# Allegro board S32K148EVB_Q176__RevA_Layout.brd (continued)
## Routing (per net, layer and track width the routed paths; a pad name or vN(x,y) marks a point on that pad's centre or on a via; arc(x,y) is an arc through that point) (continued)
PTC16/MII_RMII_RX_ER/QSPI_B_I_2: length 3.3
  TOP w0.279: v1(44,41.62) 44.37,41.99 44.37,42.03 44.55,42.21 U13.10
  TOP w0.406: R230.2 43.6,41.26 43.95,41.62 43.95,41.62 v1(44,41.62)
  BOTTOM w0.279: R230.2 43.6,41.26 43.95,41.62 43.95,41.62 v1(44,41.62)
PTC16/MII_RMII_RX_ER/QSPI_B_IO7: length 4.9
  TOP w0.279: R195.1 42.35,47.71 v1(42.41,47.66) 42.41,47.41 42.77,47.04 44.31,47.04 44.55,46.8 U13.5
  BOTTOM w0.279: v1(42.41,47.66) 42.35,47.71 R195.1
PTC17/MII_RMII_RX_DV: length 103.3
  TOP w0.406: v1(43.32,51.7) 43.32,50.21 43.37,50.16 R196.2 ; R81.2 v1(102.68,67.52)
  L6_INT_2 w0.191: v1(43.32,51.7) 43.32,50.2 44.21,49.31 44.21,47.55 50.98,40.78 55.84,40.78 56.43,41.37 83.98,41.37 84.04,41.43 87.93,45.32 87.93,51.35 88.31,51.72 93.6,57.01 93.87,57.01 93.87,57.01 96.03,57.01 96.31,57.29 96.31,57.31 98.98,59.98 98.98,60.45 95.1,64.34 95.1,66.87 94.72,67.24 94.72,71.9 94.81,71.98 v1(94.81,72.63)
  BOTTOM w0.406: v1(102.68,67.52) 102.27,67.94 102.27,70.3 101.82,70.75 98.82,70.75 96.94,72.63 v1(94.81,72.63)
PTC17/MII_RMII_RX_DV/QSPI_B_I_1: length 3.2
  TOP w0.279: U13.11 v1(45.05,41.72) 44.95,41.72 44.62,41.39 R231.2
  BOTTOM w0.279: v1(45.05,41.72) 44.95,41.72 44.62,41.39 R231.2
PTC17/MII_RMII_RX_DV/QSPI_B_I_2: length 33.1
  TOP w0.16: U8.64 v1(54.65,54.93) ; U7.56 v1(58.98,52.93)
  TOP w0.406: R231.1 v1(44.62,39.11)
  L3_INT_1 w0.191: 52.74,54.93 50.86,54.93 46.92,50.99 46.92,45.72 43.8,42.61 43.8,42.15 43.12,41.47 43.12,38.92 43.4,38.64 44.14,38.64 v1(44.62,39.11)
  L3_INT_1 w0.203: 52.74,54.93 v1(54.65,54.93)
  BOTTOM w0.16: v1(58.98,52.93) 57.39,52.93 55.39,54.93 v1(54.65,54.93)
PTC17/MII_RMII_RX_DV/QSPI_B_IO6: length 4.2
  TOP w0.279: R196.1 v1(43.37,47.75) 44.25,47.75 45.05,46.95 U13.4
  BOTTOM w0.279: v1(43.37,47.75) R196.1
PTC18/FTM7_CH4: length 47.2
  TOP w0.16: U8.83 v1(54.18,45.42)
  BOTTOM w0.191: J2.3 42.68,82.51 43.49,81.7 43.49,76.03 41.5,74.03 41.5,59.53 48.7,52.32 48.7,52.25 48.74,52.21 48.74,51.77
  BOTTOM w0.203: v1(54.18,45.42) 53.84,45.08 53.29,45.08 49.8,48.58 49.8,49.31 48.76,50.35 48.76,51.76 48.74,51.77
PTC19/FTM7_CH5/ADC0_SE25: length 71
  TOP w0.16: U8.85 v1(52.77,44.42) ; U7.72 v1(58.98,44.93)
  L3_INT_1 w0.191: 52.74,44.4 50.63,42.29 50.63,33.82 49.03,32.21 49.03,26.59 v1(48.87,26.43)
  L3_INT_1 w0.203: v1(52.77,44.42) 52.74,44.4
  L6_INT_2 w0.191: v1(48.87,26.43) 50.17,27.73 61.38,27.73 62.35,26.75 62.35,26.19 63.01,25.53 69.02,25.53 71.33,27.85 85,27.85 J5.11
  BOTTOM w0.16: v1(58.98,44.93) 58.48,44.42 v1(52.77,44.42)
PTC20/FTM7_CH6: length 48.4
  TOP w0.16: U8.86 v1(54.65,43.92)
  BOTTOM w0.191: J2.6 37.95,81.39 37.95,78.4 37.93,78.38 37.93,62.57 48.43,52.08 48.43,51.92 48.42,51.91 48.42,51.64 48.43,51.63 48.43,50.2
  BOTTOM w0.203: v1(54.65,43.92) 52.59,43.92 49.47,47.04 49.47,49.16 48.43,50.2
PTC21/FTM7_CH7/FTM7_FLT0: length 50.8
  TOP w0.16: U8.87 v1(54.18,43.42)
  BOTTOM w0.191: J2.9 35.41,81.39 35.41,76.84 34.32,75.74 34.32,65.75 37.65,62.41 37.65,62.41 48.08,51.97 48.08,50.72
  BOTTOM w0.203: v1(54.18,43.42) 54.13,43.47 53.85,43.47 53.81,43.51 53.12,43.51 53.08,43.47 52.57,43.47 48.47,47.57 48.47,49.13 48.09,49.51 48.09,50.72 48.08,50.72
PTC22/FTM7_FLT1: length 51.4
  TOP w0.16: U8.88 v1(54.65,42.92)
  BOTTOM w0.191: J2.12 35.1,81.41 35.1,76.97 34,75.88 34,65.61 47.76,51.84 47.76,50.87 47.76,50.86 47.76,50.59 47.76,50.58 47.76,49.37 48.15,48.99 48.15,47.44 52.47,43.11 52.94,43.11
  BOTTOM w0.203: v1(54.65,42.92) 53.9,42.92 53.67,43.15 53.27,43.15 53.23,43.11 52.94,43.11
PTC23/LPSPI0_SCK/ADC0_SE26: length 28.3
  TOP w0.16: v1(57.85,39.78) 57.78,39.78 57.78,40.98 ; U7.73 v1(59.79,44.12)
  L3_INT_1 w0.191: v1(57.85,39.78) 57.51,39.44 57.51,39.11 57.82,38.8 59.12,38.8 61.2,36.72 61.2,33.85 58.88,31.54 55.71,31.54 54.97,30.8 52.39,30.8 J4.1
  BOTTOM w0.16: v1(57.85,39.78) 59.79,41.72 v1(59.79,44.12)
PTC24/FTM4_CH0: length 58.6
  TOP w0.16: v1(58.32,39.27) 58.32,39.73 58.31,39.75 58.31,39.97 58.28,39.99 58.28,40.98
  BOTTOM w0.191: 52.72,42.61 52.53,42.61 47.83,47.31 47.83,48.86 47.43,49.25 47.43,51.39 47.43,51.4 47.43,51.73 41.04,58.12 40.77,58.12 40.76,58.11 40.72,58.11 33.64,65.19 33.64,72.96 30.36,76.24 30.36,81.41 J2.15
  BOTTOM w0.203: v1(58.32,39.27) 57.67,39.27 55.43,41.51 55.17,41.77 54.96,41.77 54.66,42.06 53.26,42.06 52.72,42.61
PTC25/FTM4_CH1: length 61.5
  TOP w0.16: 58.78,40.98 v1(58.78,39.79)
  BOTTOM w0.191: 40.9,57.8 39.6,57.8 27.82,69.57 27.82,81.41 J2.18
  BOTTOM w0.203: 40.9,57.8 47.1,51.59 47.1,49.13 47.5,48.73 47.5,47.17 52.45,42.23 52.54,42.23 53.06,41.71 54.52,41.71 54.86,41.36 55.08,41.36 57.65,38.79 58.52,38.79 58.8,39.07 58.8,39.77 v1(58.78,39.79)
PTC26/FTM4_CH3: length 63.4
  TOP w0.16: 59.79,40.98 v1(59.79,39.79)
  BOTTOM w0.191: 59.47,38.82 59.09,38.44 57.29,38.44 54.37,41.36 52.86,41.36 47.18,47.04 47.18,48.59 46.76,49.01 46.76,50.31 39.6,57.48 39.46,57.48 25.28,71.66 25.28,81.41 J2.21
  BOTTOM w0.203: v1(59.79,39.79) 59.79,39.14 59.47,38.82
PTC27/FTM4_CH4/FTM4_CH4/ADC0_SE: length 24.3
  TOP w0.16: U7.76 v1(61.29,44.59) ; 60.79,40.98 v1(60.79,39.79)
  L3_INT_1 w0.191: 61.24,38.62 61.52,38.34 61.52,33.72 59.02,31.22 55.84,31.22 55.1,30.48 54.61,30.48 J4.4
  L3_INT_1 w0.203: 61.24,38.62 60.79,39.07 v1(60.79,39.79)
  BOTTOM w0.16: v1(60.79,39.79) 60.79,40.31 61.29,40.81 v1(61.29,44.59)
PTC28: length 9.6
  TOP w0.203: 62.29,40.98 v1(62.29,39.3) ; U7.79 v1(62.79,44.12)
  TOP w0.279: R246.2 62.29,39.3 v1(62.29,39.3)
  BOTTOM w0.203: 62.29,38.62 v1(62.29,39.3) 62.29,40.19 62.64,40.54 62.64,40.67 62.79,40.82 v1(62.79,44.12)
  BOTTOM w0.406: 62.29,38.62 62.29,38.35 R583.2
PTC28/FTM4_CH7/FTM4_CH7/ADC0_SE: length 17.7
  TOP w0.406: v1(63.51,37.59) 63.31,37.79 R246.1
  L3_INT_1 w0.191: v1(63.51,37.59) 63.85,37.25 63.85,31.44 62.34,29.93 62.34,29.04 61.38,28.07 56.94,28.07 J4.7
PTC29/FTM5_CH2/FTM5_CH2/ADC0_SE: length 21.3
  TOP w0.16: U7.82 v1(64.29,44.59) ; 63.79,40.98 v1(63.79,39.79)
  L3_INT_1 w0.191: 63.3,38.62 62.47,37.79 62.47,32.33 59.9,29.76 59.9,29.64 59.43,29.17 J4.10
  L3_INT_1 w0.203: v1(63.79,39.79) 63.79,39.11 63.3,38.62
  BOTTOM w0.16: v1(64.29,44.59) 64.29,40.89 63.79,40.39 v1(63.79,39.79)
PTC30/FTM5_CH4/FXIO_D0/LPI2C1_S: length 40.3
  TOP w0.16: U7.84 v1(65.29,44.59) ; 64.79,40.98 v1(64.79,39.79)
  TOP w0.406: R320.1 v1(58.13,12.37) ; v1(58.15,17.71) 62.19,21.75 62.19,27.9 J4.13
  L3_INT_1 w0.191: 63.87,38.62 62.8,37.55 62.8,32.1 60.92,30.22 J4.13
  L3_INT_1 w0.203: v1(64.79,39.79) 64.79,39.14 64.27,38.62 63.87,38.62
  BOTTOM w0.16: v1(64.79,39.79) 64.79,40.25 65.29,40.75 v1(65.29,44.59)
  BOTTOM w0.406: v1(58.13,12.37) 58.13,12.96 58.15,12.98 v1(58.15,17.71)
PTC31/FTM5_CH6/FXIO_D1/LPI2C1_S: length 55.6
  TOP w0.16: U7.86 v1(66.29,44.59) ; 65.79,40.98 v1(65.79,39.79)
  TOP w0.406: R313.1 40.35,12.43 42.84,14.92 48.93,14.92 50.15,16.14 57.4,16.14 64.76,23.49 64.76,27.87 J4.16
  L3_INT_1 w0.191: 65.79,38.62 65.79,31.5 J4.16
  L3_INT_1 w0.203: 65.79,38.62 v1(65.79,39.79)
  BOTTOM w0.16: v1(65.79,39.79) 65.79,40.1 66.29,40.61 v1(66.29,44.59)
PTD0/FTM0_CH2/FTM2_CH0/TRACE_D0: length 60.3
  TOP w0.16: U7.4 v1(75.79,63.24) ; U8.8 v1(75.8,67.57)
  TOP w0.406: R122.2 95.72,60.03 v1(95.92,59.83)
  L3_INT_1 w0.191: J6.29 69.66,78.85 69.66,75.19 75.8,69.05
  L3_INT_1 w0.203: 75.8,69.05 v1(75.8,67.57)
  L6_INT_2 w0.191: v1(95.92,59.83) 95.45,59.83 80,75.28 79.3,75.28 77.26,77.32 77.26,77.88 76.3,78.85 75.73,78.85 74.72,79.86 74.72,80.42 74.08,81.07 69.64,81.07 J6.29
  BOTTOM w0.16: v1(75.79,63.24) 75.79,67.11 75.8,67.11 v1(75.8,67.57)
PTD1/FTM0_CH3/LPSPI1_SIN/FTM2_C: length 109.7
  TOP w0.16: U7.3 v1(76.29,62.77) ; U8.7 v1(76.3,68.04)
  TOP w0.406: R323.1 v1(65.75,12.33)
  L3_INT_1 w0.191: v1(92.44,68.74) 88.96,65.26 84.47,65.26 v1(84.09,65.64) ; J5.18 93.94,24.16 81.32,11.54 66.54,11.54 v1(65.75,12.33)
  L6_INT_2 w0.191: v1(84.09,65.64) 81.77,67.96 81.77,68.08 81.33,68.52 76.77,68.52 v1(76.3,68.04)
  BOTTOM w0.16: v1(76.3,68.04) 76.3,67.58 76.29,67.58 v1(76.29,62.77)
  BOTTOM w0.406: v1(92.44,68.74) 92.44,51.04 96.44,47.04 96.44,33.65 95.24,32.45 95.24,27.93 J5.18
PTD2/FTM3_CH4/LPSPI1_SOUT/FXIO_: length 63
  TOP w0.16: 74.8,40.98 v1(74.8,39.32) ; U7.102 v1(74.29,44.59)
  L6_INT_2 w0.191: 83.93,48.2 85.16,49.42 85.16,50.83 87.23,52.9 87.23,66.31 81.22,72.32 75.14,72.32 71.08,76.38 J6.25
  L6_INT_2 w0.203: v1(74.29,44.59) 74.29,43.94 74.95,43.29 79.14,43.29 82.24,46.38 82.65,46.38 82.67,46.37 83.35,46.37 83.65,46.67 83.65,47.92 83.93,48.2
  BOTTOM w0.16: v1(74.8,39.32) 74.8,41.84 74.29,42.34 v1(74.29,44.59)
PTD3/FTM3_CH5/LPSPI1_PCS0/FXIO_: length 69.8
  TOP w0.16: U7.101 v1(73.79,44.12) ; 74.3,40.98 v1(74.3,39.79)
  L6_INT_2 w0.191: J6.28 69.64,78.53 71.54,78.53 72.18,77.88 72.18,76.04 75.58,72.64 81.36,72.64 89.92,64.08 89.92,54.68 87.91,52.67 86.94,51.7 86.94,48.71 86.23,48 85.38,48 84.79,47.41 84.79,45.6 82.12,42.94 74.5,42.94 73.79,43.65 v1(73.79,44.12)
  BOTTOM w0.16: v1(74.3,39.79) 74.3,41.45 73.79,41.95 v1(73.79,44.12)
PTD4/FTM0_FLT3/ADC1_SE6: length 45.7
  TOP w0.16: U7.100 v1(73.29,44.59) ; 73.8,40.98 v1(73.8,39.32)
  L3_INT_1 w0.191: J4.2 51.86,25.53 53.76,25.53 54.73,26.5 54.73,27.07 55.39,27.73 56.3,27.73 56.95,27.07 56.95,26.5 57.93,25.53 69,25.53 70.9,27.44 70.9,35.73 73.8,38.62
  L3_INT_1 w0.203: 73.8,38.62 v1(73.8,39.32)
  BOTTOM w0.16: v1(73.8,39.32) 73.8,40.93 73.29,41.44 v1(73.29,44.59)
PTD5/MII_TXD3: length 104
  TOP w0.406: R115.2 103.57,61.17 103.22,60.82 v1(102.86,60.82) ; R270.2 v1(41.21,32.55)
  L6_INT_2 w0.191: v1(41.21,32.55) 41.6,32.94 41.6,33.07 41.24,33.43 41.24,33.56 41.33,33.65 41.46,33.65 41.82,33.29 41.95,33.29 42.44,33.79 42.84,33.79 42.94,33.69 42.94,33.13 43.03,33.04 43.16,33.04 43.26,33.13 43.26,33.69 43.35,33.79 43.48,33.79 43.57,33.69 43.57,33.13 43.67,33.04 43.8,33.04 43.89,33.13 43.89,33.69 43.98,33.79 46.35,33.79 46.87,33.27 49.01,33.27 49.56,33.82 54.85,33.82 56.1,35.06 56.69,35.06 56.79,34.97 56.79,34.76 56.88,34.67 57.01,34.67 57.1,34.76 57.1,34.97 57.2,35.06 60.6,35.06 61.57,34.09 63.96,34.09 64.05,34 64.05,33.47 64.14,33.38 64.27,33.38 64.37,33.47 64.37,34 64.46,34.09 65.45,34.09 66.33,34.97 74.44,34.97 74.88,35.41 75.01,35.41 75.32,35.1 75.45,35.1 75.55,35.19 75.55,35.32 75.24,35.63 75.24,35.76 75.33,35.86 75.46,35.86 75.77,35.55 75.9,35.55 76,35.64 76,35.77 75.69,36.08 75.69,36.21 75.78,36.31 75.91,36.31 76.22,36 76.35,36 76.44,36.09 76.44,36.22 76.14,36.53 76.14,36.66 76.47,36.99 77.05,36.99 77.14,36.9 77.14,36.01 77.23,35.92 77.36,35.92 77.46,36.01 77.46,36.9 77.55,36.99 77.68,36.99 77.77,36.9 77.77,36.01 77.87,35.92 78,35.92 78.09,36.01 78.09,36.9 78.18,36.99 78.32,36.99 78.41,36.9 78.41,36.01 78.5,35.92 78.63,35.92 78.73,36.01 78.73,36.9 78.82,36.99 79.14,36.99 79.23,36.9 79.23,35.84 79.32,35.75 79.45,35.75 79.55,35.84 79.55,36.9 79.64,36.99 79.77,36.99 79.86,36.9 79.86,35.84 79.96,35.75 80.09,35.75 80.18,35.84 80.18,36.9 80.28,36.99 80.41,36.99 80.5,36.9 80.5,35.84 80.59,35.75 80.72,35.75 80.82,35.84 80.82,36.9 80.91,36.99 81.23,36.99 81.32,36.9 81.32,36.41 81.41,36.32 81.55,36.32 81.64,36.41 81.64,36.9 81.73,36.99 82.73,36.99 83.17,37.43 83.75,38.01 85.56,38.01 90.79,43.24 90.79,46.78 92.09,48.07 92.09,48.09 98.26,54.26 99.91,54.26 100.37,54.72 100.37,54.85 103.43,57.9 103.43,60.25 v1(102.86,60.82)
PTD5/MII_TXD3/QSPI_B_IO2: length 49.6
  TOP w0.16: U7.46 v1(58.98,57.93) ; U8.54 v1(54.65,59.94)
  L3_INT_1 w0.191: v1(54.65,59.94) 53.44,59.94 53.15,59.65 51.75,59.65 51.55,59.45 46.55,59.45 41.82,54.72 v1(40.42,54.72)
  L6_INT_2 w0.191: v1(41.63,40) 39.7,40 37.97,38.27 37.53,38.27 37.19,38.62 37.19,43.16 37.29,43.27 37.29,43.29 41.94,47.93 41.94,49 41.65,49.29 41.37,49.29 41.09,49.57 41.09,49.97 41.32,50.19 41.32,53.83 v1(40.42,54.72)
  BOTTOM w0.16: v1(54.65,59.94) 55.11,59.94 57.12,57.93 v1(58.98,57.93)
  BOTTOM w0.406: R580.1 41.36,39.74 v1(41.63,40)
PTD5/MII_TXD3/QSPI_B_IO2__A: length 2.9
  TOP w0.279: U14.11 39.84,41.18 40.02,41.36 v1(40.02,41.41)
  BOTTOM w0.279: R570.2 40.02,41.79 v1(40.02,41.41)
  BOTTOM w0.406: R580.2 40.4,41.03 v1(40.02,41.41)
PTD5/MII_TXD3/QSPI_B_IO2__B: length 4.6
  TOP w0.279: R270.1 40.8,34.74 40.65,34.74 v1(40.14,35.24) 40.14,35.76 39.84,36.07 U14.4
  BOTTOM w0.279: R270.1 40.8,34.74 40.65,34.74 v1(40.14,35.24)
PTD6/MII_TXD2: length 104.3
  TOP w0.406: R111.2 103.82,62.19 103.48,62.53 103.48,62.53 v1(103.48,62.53) ; R269.2 v1(40.2,32.56)
  L3_INT_1 w0.191: v1(107.1,58.91) 103.82,62.19 103.82,62.19 v1(103.48,62.53)
  L6_INT_2 w0.191: v1(107.1,58.91) 107.1,56.76 102.23,51.89 100.15,51.89 98.99,50.73 98.99,45.86 98.77,45.64 98.63,45.64 97.91,46.36 97.78,46.36 97.69,46.26 97.69,46.13 98.41,45.41 98.41,45.28 98.32,45.19 98.18,45.19 97.47,45.91 97.33,45.91 97.24,45.81 97.24,45.68 97.96,44.96 97.96,44.83 97.87,44.74 97.74,44.74 97.02,45.46 96.88,45.46 96.79,45.37 96.79,45.23 97.51,44.51 97.51,44.38 97.42,44.29 97.29,44.29 96.57,45.01 96.44,45.01 96.34,44.92 96.34,44.79 97.06,44.07 97.06,43.93 94.93,41.8 94.8,41.8 94.24,42.36 94.1,42.36 94.01,42.27 94.01,42.14 94.57,41.58 94.57,41.44 94.48,41.35 94.35,41.35 93.79,41.91 93.66,41.91 93.56,41.82 93.56,41.69 94.12,41.13 94.12,41 94.03,40.9 93.9,40.9 93.34,41.46 93.21,41.46 93.11,41.37 93.11,41.24 93.67,40.68 93.67,40.55 84.98,31.86 79.65,31.86 79.4,32.11 60.8,32.11 60.73,32.19 59.76,32.19 59.1,32.85 58.44,32.85 58.42,32.83 57.51,32.83 57.25,33.09 56.57,33.09 55.87,32.39 51.23,32.39 50.83,32 40.76,32 v1(40.2,32.56)
PTD6/MII_TXD2/QSPI_B_IO1: length 47.3
  TOP w0.16: U8.53 v1(54.18,60.44) ; U7.45 v1(59.45,58.43)
  TOP w0.279: v1(36.31,42.96) 36.59,42.96 36.6,42.95 38.49,42.95 38.68,43.14 R223.1
  L3_INT_1 w0.191: v1(36.31,42.96) 34.26,45.01 34.26,50.12 36.1,51.96 36.1,53.36 35.77,53.7 35.77,54.82 36.23,55.29 37.84,55.29 37.99,55.13 38.52,55.13 39.03,55.64 41.22,55.64 46.06,60.48 51.5,60.48 51.9,60.08 52.74,60.08
  L3_INT_1 w0.203: 52.74,60.08 53.09,60.08 53.37,60.36 54.1,60.36 v1(54.18,60.44)
  BOTTOM w0.16: v1(59.45,58.43) 57.1,58.43 55.19,60.34 55.06,60.44 v1(54.18,60.44)
PTD6/MII_TXD2/QSPI_B_IO1__A: length 3.1
  TOP w0.279: U14.12 39.34,40.98 v1(38.94,41.38) 38.96,41.39 38.96,41.75 R223.2
  BOTTOM w0.279: v1(38.94,41.38) 38.96,41.39 38.96,41.75 R223.2
PTD6/MII_TXD2/QSPI_B_IO1__B: length 4.1
  TOP w0.279: U14.3 v1(39.34,35.16) 39.71,34.8 39.73,34.8 R269.1
  BOTTOM w0.279: R269.1 39.73,34.8 39.71,34.8 v1(39.34,35.16)
PTD7/MII_RMII_TXD1: length 103.5
  TOP w0.406: R109.2 v1(103.57,63.21) ; R272.2 v1(44.46,33.31)
  L6_INT_2 w0.191: v1(44.46,33.31) 46.28,33.31 46.64,32.95 49.14,32.95 49.69,33.5 54.98,33.5 55.58,34.1 55.96,34.1 56.05,34 56.05,33.48 56.14,33.39 56.27,33.39 56.37,33.48 56.37,34 56.46,34.1 59.22,34.1 60.5,32.82 60.99,32.82 61.07,32.74 79.71,32.74 80.66,33.69 82.59,33.69 82.68,33.6 82.68,32.64 82.77,32.55 82.91,32.55 83,32.64 83,33.6 83.09,33.69 83.22,33.69 83.32,33.6 83.32,32.64 83.41,32.55 83.54,32.55 83.63,32.64 83.63,33.6 83.73,33.69 83.89,33.69 84.41,34.21 84.55,34.21 84.9,33.86 85.03,33.86 85.13,33.95 85.13,34.08 84.77,34.44 84.77,34.57 84.86,34.66 85,34.66 85.35,34.3 85.48,34.3 85.58,34.4 85.58,34.53 85.22,34.89 85.22,35.02 86.54,36.33 86.67,36.33 87.03,35.98 87.16,35.98 87.25,36.07 87.25,36.2 86.89,36.56 86.89,36.69 86.99,36.78 87.12,36.78 87.47,36.43 87.61,36.43 87.7,36.52 87.7,36.65 87.34,37.01 87.34,37.14 87.44,37.23 87.57,37.23 87.92,36.88 88.05,36.88 88.15,36.97 88.15,37.1 87.79,37.46 87.79,37.59 87.88,37.68 88.02,37.68 88.37,37.33 88.5,37.33 88.6,37.42 88.6,37.55 88.24,37.91 88.24,38.04 88.33,38.13 88.47,38.13 88.82,37.77 88.95,37.77 89.05,37.87 89.05,38 88.69,38.36 88.69,38.49 88.78,38.58 88.91,38.58 89.27,38.22 89.4,38.22 89.5,38.32 89.5,38.45 89.14,38.8 89.14,38.94 89.23,39.03 89.36,39.03 89.72,38.67 89.85,38.67 89.94,38.77 89.94,38.9 89.59,39.25 89.59,39.39 89.68,39.48 89.81,39.48 90.17,39.12 90.3,39.12 90.39,39.22 90.39,39.35 90.04,39.7 90.04,39.83 90.13,39.93 90.26,39.93 90.62,39.57 90.75,39.57 90.84,39.66 90.84,39.8 90.49,40.15 90.49,40.28 90.58,40.38 90.71,40.38 91.07,40.02 91.2,40.02 91.29,40.11 91.29,40.24 90.94,40.6 90.94,40.73 91.03,40.83 91.16,40.83 91.52,40.47 91.65,40.47 91.74,40.56 91.74,40.69 91.38,41.05 91.38,41.18 92.1,41.9 92.1,46.29 93.36,47.55 93.36,47.56 98.34,52.55 100,52.55 101.64,54.2 101.64,54.32 104.7,57.38 104.7,62.08 104.47,62.3 104.47,62.43 104.57,62.52 104.57,62.66 104.47,62.75 104.34,62.75 104.25,62.66 104.12,62.66 v1(103.57,63.21)
PTD7/MII_RMII_TXD1//QSPI_A_IO1: length 42.6
  TOP w0.16: U8.52 v1(54.65,60.94) ; U7.44 v1(58.98,58.93)
  TOP w0.406: v1(43.19,42.23) 43.19,42.26 43.18,42.26 43.18,42.28 R224.1
  L3_INT_1 w0.191: 52.74,60.44 52.11,60.44 51.75,60.8 43.78,60.8 v1(39.1,56.12)
  L3_INT_1 w0.203: v1(54.65,60.94) 53.93,60.94 53.73,60.74 53.25,60.74 52.94,60.44 52.74,60.44
  L6_INT_2 w0.191: v1(39.1,56.12) 39.7,56.12 42.49,53.33 42.49,50.09 43.85,48.73 43.85,42.89 v1(43.19,42.23)
  BOTTOM w0.16: v1(54.65,60.94) 55.19,60.94 57.2,58.93 v1(58.98,58.93)
PTD7/MII_RMII_TXD1//QSPI_A_IO1_: length 7.5
  TOP w0.279: R272.1 R271.1 42.23,34.96 41.85,35.34 v1(40.96,35.34) 40.59,35.71 40.59,36.14 40.34,36.39 U14.5
  BOTTOM w0.279: R272.1 42.23,35.34 v1(40.96,35.34)
PTD7/MII_RMII_TXD1//QSPI_A_IO_1: length 3.5
  TOP w0.279: v1(40.98,41.45) 40.61,41.08 40.58,41.08 40.34,40.85 U14.10
  TOP w0.406: R224.2 41.41,41.69 41.15,41.43 41.15,41.45 v1(40.98,41.45)
  BOTTOM w0.406: R573.2 41.07,41.45 v1(40.98,41.45)
PTD7/QSPI_A_IO1: length 48.1
  TOP w0.406: v1(42.23,32.55) R271.2
  BOTTOM w0.254: v1(42.23,32.55) 42.74,32.04 45.28,32.04 45.66,32.42 46.19,32.42 46.31,32.53 46.31,33.1 46.42,33.21 46.57,33.21 46.69,33.1 46.69,32.53 46.8,32.42 46.96,32.42 47.07,32.53 47.07,33.1 47.18,33.21 47.34,33.21 47.45,33.1 47.45,32.53 47.56,32.42 47.72,32.42 47.83,32.53 47.83,33.1 47.94,33.21 48.1,33.21 48.21,33.1 48.21,32.53 48.32,32.42 48.48,32.42 48.59,32.53 48.59,33.1 48.7,33.21 48.86,33.21 48.97,33.1 48.97,32.53 49.08,32.42 49.24,32.42 49.35,32.53 49.35,33.1 49.46,33.21 49.62,33.21 49.73,33.1 49.73,32.53 49.85,32.42 50.23,32.42 50.48,32.17 50.48,31.46 50.23,31.2 49.85,31.2 49.73,31.31 49.73,31.93 49.62,32.04 49.46,32.04 49.35,31.93 49.35,31.31 49.24,31.2 49.08,31.2 48.97,31.31 48.97,31.93 48.86,32.04 48.7,32.04 48.59,31.93 48.59,31.31 48.48,31.2 48.32,31.2 48.21,31.31 48.21,31.93 48.1,32.04 47.94,32.04 47.83,31.93 47.83,31.31 47.72,31.2 47.56,31.2 47.45,31.31 47.45,31.93 47.34,32.04 47.18,32.04 47.07,31.93 47.07,31.31 46.96,31.2 46.8,31.2 46.69,31.31 46.69,31.93 46.57,32.04 46.42,32.04 46.31,31.93 46.31,31.31 46.19,31.2 45.66,31.2 45.55,31.31 45.55,31.55 45.44,31.66 45.28,31.66 45.17,31.55 45.17,31.31 45.06,31.2 44.9,31.2 44.79,31.31 44.79,31.55 44.68,31.66 44.52,31.66 44.41,31.55 44.41,31.31 44.3,31.2 44.14,31.2 44.03,31.31 44.03,31.55 43.92,31.66 43.76,31.66 43.65,31.55 43.65,31.31 43.54,31.2 43.38,31.2 43.27,31.31 43.27,31.55 43.15,31.66 43,31.66 42.89,31.55 42.89,31.31 42.77,31.2 42.62,31.2 42.5,31.31 42.5,31.55 42.39,31.66 42.23,31.66 42.12,31.55 42.12,31.31 42.01,31.2 41.85,31.2 41.74,31.31 41.74,31.55 41.63,31.66 41.47,31.66 41.36,31.55 41.36,31.31 41.25,31.2 41.09,31.2 40.98,31.31 40.98,31.55 40.87,31.66 40.71,31.66 40.6,31.55 40.6,31.31 40.49,31.2 40.33,31.2 40.22,31.31 40.22,31.55 40.11,31.66 39.95,31.66 39.84,31.55 39.84,31.31 39.73,31.2 38.62,31.2 38.11,31.71 38.11,36.23 R585.1
PTD8/MII_RXD3: length 104.6
  TOP w0.406: R58.2 v1(103.61,72.6) ; R197.2 v1(44.39,50.26)
  L6_INT_2 w0.191: v1(44.39,50.26) 44.39,49.79 44.54,49.64 44.54,47.67 45.95,46.26 46.08,46.26 46.83,47.01 46.96,47.01 47.05,46.91 47.05,46.78 46.31,46.04 46.31,45.91 46.4,45.81 46.53,45.81 47.28,46.56 47.41,46.56 47.5,46.47 47.5,46.33 46.76,45.59 46.76,45.46 46.85,45.36 46.98,45.36 47.73,46.11 47.86,46.11 47.95,46.02 47.95,45.89 47.2,45.14 47.2,45.01 51.09,41.13 55.7,41.13 56.29,41.71 83.74,41.71 87.62,45.59 87.62,51.48 88.17,52.03 88.18,52.03 94.11,57.97 96.52,57.97 98.31,59.76 98.31,60.56 94.78,64.09 94.78,66.74 94.37,67.14 94.37,72.39 94.33,72.43 94.33,72.83 94.37,72.87 v1(94.37,73.8)
  BOTTOM w0.406: v1(103.61,72.6) 103.02,72.6 102.92,72.5 99.76,72.5 97.93,74.33 94.91,74.33 v1(94.37,73.8)
PTD8/MII_RXD3/QSPI_B_IO5: length 39.8
  TOP w0.16: U7.55 v1(59.45,53.43) ; U8.63 v1(54.18,55.43)
  TOP w0.406: v1(45.63,39.11) R232.1
  L3_INT_1 w0.191: v1(45.63,39.11) 44.84,38.32 42.72,38.32 42.11,38.93 42.11,41.91 41.6,42.42 41.6,47.81 42.36,48.58 42.36,49.86 47.93,55.43 52.74,55.43
  L3_INT_1 w0.203: v1(54.18,55.43) 52.74,55.43
  BOTTOM w0.16: v1(59.45,53.43) 57.37,53.43 55.37,55.43 v1(54.18,55.43)
PTD8/MII_RXD3/QSPI_B_IO5__A: length 3.4
  TOP w0.279: U13.12 45.55,42.13 v1(46.14,41.54) 45.63,41.03 R232.2
  BOTTOM w0.279: R232.2 45.63,41.26 45.91,41.54 v1(46.14,41.54)
PTD8/MII_RXD3/QSPI_B_IO5__B: length 3.9
  TOP w0.279: U13.3 45.55,47.34 v1(45.22,47.66) R197.1
  BOTTOM w0.279: v1(45.22,47.66) R197.1
PTD9/MII_RXD2: length 104.3
  TOP w0.406: R62.2 v1(103.61,71.59) ; R198.2 45.4,50.02 45.17,50.25 45.17,50.25 45.17,50.25 45.17,50.24 v1(45.17,50.24)
  L6_INT_2 w0.191: v1(45.17,50.24) 45.17,49.25 49.68,44.74 49.68,44.6 49.12,44.05 49.12,43.91 49.22,43.82 49.35,43.82 49.91,44.38 50.04,44.38 50.13,44.29 50.13,44.15 49.57,43.6 49.57,43.47 49.67,43.37 49.8,43.37 50.35,43.93 50.49,43.93 50.58,43.84 50.58,43.71 50.02,43.15 50.02,43.02 50.11,42.92 50.25,42.92 50.8,43.48 50.94,43.48 51.03,43.39 51.03,43.26 50.47,42.7 50.47,42.57 50.56,42.47 50.7,42.47 51.25,43.03 51.38,43.03 51.48,42.94 51.48,42.81 50.92,42.25 50.92,42.12 51.01,42.03 51.14,42.03 51.7,42.58 51.83,42.58 51.93,42.49 51.93,42.36 51.37,41.8 51.37,41.67 51.46,41.58 51.59,41.58 52.15,42.13 52.28,42.13 52.95,41.47 55.56,41.47 56.14,42.05 83.6,42.05 87.3,45.76 87.3,51.61 88.04,52.35 93.98,58.28 94.24,58.28 94.24,58.28 96.07,58.28 96.51,58.72 96.51,59.92 94.41,62.01 94.41,65.97 94.04,66.35 94.04,69.65 93.76,69.92 v1(93.76,71.05)
  BOTTOM w0.406: v1(93.76,71.05) 93.76,72.71 94.27,73.21 94.75,73.21 95.21,73.67 97.34,73.67 99.42,71.59 v1(103.61,71.59)
PTD9/MII_RXD2/QSPI_B_IO4: length 27.7
  TOP w0.16: U8.62 v1(54.65,55.93) ; U7.54 v1(58.98,53.93)
  TOP w0.406: v1(47.71,40.24) 47.33,39.86 R233.1
  L3_INT_1 w0.191: v1(47.71,40.24) 48.91,41.44 48.91,45.63 v1(53.51,50.23)
  L6_INT_2 w0.191: v1(54.65,55.93) 54.01,55.93 53.51,55.43 v1(53.51,50.23)
  BOTTOM w0.16: v1(54.65,55.93) 55.5,55.93 57.5,53.93 v1(58.98,53.93)
PTD9/MII_RXD2/QSPI_B_IO4__A: length 4
  TOP w0.279: R233.2 47.06,41.29 47.06,41.6 v1(47.18,41.72) 46.86,42.03 46.54,42.03 46.05,42.53 U13.13
  BOTTOM w0.279: R233.2 46.65,41.34 47.03,41.72 v1(47.18,41.72)
PTD9/MII_RXD2/QSPI_B_IO4__B: length 3.7
  TOP w0.279: R198.1 45.96,47.94 45.96,47.6 v1(45.99,47.6) 45.99,47.01 46.05,46.96 U13.2
  BOTTOM w0.279: R198.1 45.99,47.91 v1(45.99,47.6)
PTD10/MII_RX_CLK: length 106
  TOP w0.406: v1(57.63,37.21) 57.16,37.68 R250.2 ; R96.2 102.98,65.36 v1(102.68,65.06) ; R79.2 v1(103.16,68.54) ; R137.2 v1(102.63,58.63)
  L3_INT_1 w0.191: v1(103.16,68.54) 103.16,65.54 v1(102.68,65.06) 102.16,64.54 102.16,59.1 v1(102.63,58.63)
  L6_INT_2 w0.191: 82.84,38.62 82.17,37.95 76.06,37.95 74.12,36 70.72,36 69.45,37.27 68.91,37.27 68.81,37.36 68.81,37.7 68.72,37.8 68.59,37.8 68.5,37.7 68.5,37.36 68.4,37.27 68.27,37.27 68.18,37.36 68.18,37.7 68.09,37.8 67.95,37.8 67.86,37.7 67.86,37.36 67.77,37.27 67.64,37.27 67.54,37.36 67.54,37.7 67.45,37.8 67.32,37.8 67.23,37.7 67.23,37.36 67.13,37.27 67,37.27 66.91,37.36 66.91,37.7 66.82,37.8 66.68,37.8 66.59,37.7 66.59,37.36 66.5,37.27 66.19,37.27 65.85,36.92 65.72,36.92 65.11,37.53 64.98,37.53 64.89,37.44 64.89,37.31 65.49,36.7 65.49,36.57 65.4,36.47 65.27,36.47 64.66,37.08 64.53,37.08 64.44,36.99 64.44,36.86 65.04,36.25 65.04,36.12 64.95,36.03 64.82,36.03 64.21,36.63 64.08,36.63 63.99,36.54 63.99,36.41 64.59,35.8 64.59,35.67 63.97,35.04 63.14,35.04 62.86,35.32 62.86,35.51 60.57,37.8 60.22,37.8 60.13,37.9 60.13,37.99 60.04,38.08 59.91,38.08 59.81,37.99 59.81,37.9 59.72,37.8 59.59,37.8 59.49,37.9 59.49,37.99 59.4,38.08 59.27,38.08 59.18,37.99 59.18,37.9 59.08,37.8 58.95,37.8 58.86,37.9 58.86,37.99 58.77,38.08 58.64,38.08 58.54,37.99 58.54,37.9 58.45,37.8 58.23,37.8 v1(57.63,37.21) ; 83.93,39.13 85.34,39.13 89.84,43.64 89.84,47.17 91.14,48.47 91.14,48.49 92.47,49.82 92.47,49.95 92.22,50.2 92.22,50.34 92.32,50.43 92.45,50.43 92.7,50.18 92.83,50.18 92.92,50.27 92.92,50.4 92.67,50.65 92.67,50.78 92.76,50.88 92.9,50.88 93.15,50.63 93.28,50.63 93.37,50.72 93.37,50.85 93.12,51.1 93.12,51.23 93.21,51.33 93.34,51.33 93.59,51.08 93.73,51.08 94.48,51.83 94.48,53.59 95.05,54.17 95.18,54.17 95.93,53.42 96.06,53.42 96.16,53.51 96.16,53.64 95.41,54.39 95.41,54.52 95.5,54.62 95.63,54.62 96.38,53.86 96.51,53.86 96.61,53.96 96.61,54.09 95.86,54.84 95.86,54.97 95.95,55.06 96.08,55.06 96.83,54.31 96.96,54.31 97.06,54.41 97.06,54.54 96.3,55.29 96.3,55.42 96.4,55.51 96.53,55.51 97.28,54.76 97.41,54.76 97.5,54.86 97.5,54.99 96.75,55.74 96.75,55.87 96.85,55.96 96.98,55.96 97.73,55.21 97.86,55.21 97.95,55.3 97.95,55.44 97.2,56.19 97.2,56.32 97.3,56.41 97.43,56.41 98.18,55.66 98.31,55.66 98.4,55.75 98.4,55.89 97.65,56.64 97.65,56.77 99.52,58.63 100.93,58.63 101.02,58.54 101.02,57.54 101.12,57.44 101.25,57.44 101.34,57.54 101.34,58.54 101.44,58.63 101.57,58.63 101.66,58.54 101.66,57.54 101.75,57.44 101.88,57.44 101.98,57.54 101.98,58.54 102.07,58.63 v1(102.63,58.63)
  L6_INT_2 w0.203: 82.84,38.62 83.36,39.13 83.93,39.13
PTD10/MII_RX_CLK/QSPI_A_SCK: length 53.9
  TOP w0.16: U7.49 v1(59.45,56.43) ; U8.57 v1(54.18,58.43)
  TOP w0.406: v1(45.87,38.46) 45.87,38.46 46.11,38.69 R243.1
  L3_INT_1 w0.191: 52.74,58.43 47.86,58.43 46.97,57.55 46.52,57.55 42.18,53.2 40.98,53.2 39.62,51.84 39.62,51.17 39.16,50.71 39.16,48.27 39.33,48.1 39.33,41.66 39.42,41.57 39.42,39.82 42.19,37.05 42.64,37.05 45.16,34.54 46.14,34.54 46.96,35.35 46.96,36.6 46.42,37.14 46.42,37.94 45.9,38.46 v1(45.87,38.46)
  L3_INT_1 w0.203: 52.74,58.43 v1(54.18,58.43)
  BOTTOM w0.16: v1(54.18,58.43) 55.15,58.43 57.16,56.43 v1(59.45,56.43)
PTD10/MII_RX_CLK/QSPI_A_SCK__A: length 4
  TOP w0.229: 48.09,38.69 48.3,38.49 v1(48.86,38.49) 49.39,37.96 49.39,37.17 49.42,37.15 49.42,37.12 49.63,36.91 U16.10
  BOTTOM w0.229: v1(48.86,38.49) 48.3,38.49 48.09,38.69
PTD10/MII_RX_CLK/QSPI_A_SCK__B: length 5.1
  TOP w0.203: 55.59,38.62 R244.1
  TOP w0.279: U16.5 53.95,36.91 v1(54.65,37.6) 55.51,37.6 R250.1
  TOP w0.406: R250.1 55.59,38.62
  BOTTOM w0.406: R587.2 55.59,37.22 55.23,37.58 54.67,37.58 v1(54.65,37.6)
PTD10/QSPI_A_SCK: length 48.6
  TOP w0.203: R244.2 55.86,39.44 54.84,39.44 v1(54.5,39.1)
  L3_INT_1 w0.191: v1(36.89,34.4) 40.9,34.4 42.46,35.96 v1(42.46,36.43)
  L6_INT_2 w0.191: v1(42.46,36.43) 42.93,36.43 43.7,37.2 46.55,37.2 46.64,37.3 46.64,37.66 46.74,37.75 46.87,37.75 46.96,37.66 46.96,37.3 47.05,37.2 47.19,37.2 47.28,37.3 47.28,37.66 47.37,37.75 47.5,37.75 47.6,37.66 47.6,37.3 47.69,37.2 50.3,37.2 50.39,37.3 50.39,38.42 50.49,38.52 50.62,38.52 50.71,38.42 50.71,37.3 50.8,37.2 50.94,37.2 51.03,37.3 51.03,38.42 51.12,38.52 51.25,38.52 51.35,38.42 51.35,37.3 51.44,37.2 51.78,37.2 53.2,38.62
  L6_INT_2 w0.203: 53.2,38.62 53.68,39.1 v1(54.5,39.1)
  BOTTOM w0.406: v1(36.89,34.4) 36.89,32.6 36.49,32.19 33.46,32.19 33.03,32.62 31.4,32.62 30.41,33.61 23.15,33.61 22.75,34.02 22.75,35.88 23.15,36.28 R591.1
PTD11/MII_RMII_TX_CLK: length 105.1
  TOP w0.279: R210.2 36.88,43.99 36.6,43.99 35.57,42.96 v1(34.89,42.96)
  TOP w0.406: v1(102.64,59.55) 102.65,59.55 103.14,60.03 R123.2
  L6_INT_2 w0.191: v1(102.64,59.55) 99.91,59.55 97.26,56.9 97.26,56.9 96.43,56.06 96.42,56.06 96.33,55.97 93.9,55.97 91.77,53.84 91.77,53.71 92.44,53.04 92.44,52.91 92.34,52.82 92.21,52.82 91.55,53.48 91.42,53.48 91.33,53.39 91.33,53.26 91.99,52.59 91.99,52.46 91.89,52.37 91.76,52.37 91.1,53.03 90.97,53.03 90.88,52.94 90.88,52.81 91.54,52.15 91.54,52.01 91.45,51.92 91.31,51.92 90.65,52.58 90.52,52.58 90.43,52.49 90.43,52.36 91.09,51.7 91.09,51.57 91,51.47 90.87,51.47 90.2,52.13 90.07,52.13 88.89,50.95 88.89,44.03 85.19,40.34 56.86,40.34 56.27,39.76 50.57,39.76 49.6,40.72 47.52,40.72 47.27,40.47 43.31,40.47 41.88,39.04 39.64,39.04 38.23,37.63 37.27,37.63 35.85,39.05 35.85,42 v1(34.89,42.96)
  BOTTOM w0.406: v1(102.64,59.55) 103.62,59.55 104.41,60.34 104.41,63.74 103.68,64.46 R514.2
PTD11/MII_RMII_TX_CLK/QSPI_A__1: length 76.8
  TOP w0.16: U7.48 v1(58.98,56.93) ; U8.56 v1(54.65,58.93)
  TOP w0.406: R173.1 v1(37.17,54.18) ; R141.2 v1(95.83,57.49)
  L3_INT_1 w0.191: v1(95.83,57.49) 95.83,57.97 93.94,59.86 84.4,59.86 v1(83.86,59.32) ; v1(37.17,54.18) 37.51,53.84 41.92,53.84 46.89,58.81 52.62,58.81 52.74,58.93
  L3_INT_1 w0.203: v1(54.65,58.93) 52.74,58.93
  L6_INT_2 w0.191: v1(83.86,59.32) 84.99,60.45 84.99,62.1 82.84,64.25 82.29,64.25 81.4,65.14 79.13,65.14 78.85,64.86 78.85,63.67 78.18,63 77.3,63 76.19,61.9 75.51,61.9 70.54,56.93 v1(58.98,56.93)
  BOTTOM w0.16: v1(58.98,56.93) 57.16,56.93 55.16,58.93 v1(54.65,58.93)
PTD11/MII_RMII_TX_CLK/QSPI_A__2: length 3.6
  TOP w0.279: U11.3 v1(38.07,46.09) 38.07,45.42 R211.1 R210.1
  BOTTOM w0.279: v1(38.07,46.09) 38.07,45.42 R211.1
PTD11/MII_RMII_TX_CLK/QSPI_A_IO: length 3.8
  TOP w0.279: U11.12 38.07,51.5 38.16,51.6 38.16,51.6 v1(38.15,51.6) 37.78,51.97 37.61,51.97 R173.2
  BOTTOM w0.279: v1(38.15,51.6) 37.78,51.97 37.61,51.97 R173.2
PTD11/QSPI_A_IO0: length 49.1
  TOP w0.279: R211.2 37.38,43.47 v1(36.82,43.47)
  BOTTOM w0.254: v1(36.82,43.47) 36.08,44.21 35.92,44.21 35.21,43.51 35.06,43.51 34.94,43.62 34.94,43.78 35.65,44.48 35.65,44.64 35.22,45.07 33.74,45.07 33.48,44.82 33.48,44.32 33.37,44.21 32.51,44.21 32.4,44.1 32.4,43.94 32.51,43.83 33.37,43.83 33.48,43.72 33.48,42.47 32.96,41.95 32.8,41.95 32.37,42.39 32.21,42.39 32.1,42.28 32.1,42.12 32.54,41.68 32.54,41.52 32.26,41.25 32.11,41.25 31.27,42.09 31.11,42.09 31,41.98 31,41.82 31.84,40.98 31.84,40.83 31.73,40.71 31.57,40.71 30.73,41.55 30.57,41.55 30.46,41.44 30.46,41.29 31.3,40.45 31.3,40.29 31.19,40.18 31.03,40.18 30.19,41.02 30.03,41.02 29.92,40.9 29.92,40.75 30.76,39.91 30.76,39.75 30.65,39.64 30.49,39.64 29.65,40.48 29.49,40.48 29.38,40.36 29.38,40.21 30.22,39.37 30.22,39.21 29.95,38.94 29.79,38.94 28.8,39.94 28.64,39.94 28.53,39.83 28.53,39.67 29.52,38.67 29.52,38.51 29.41,38.4 29.25,38.4 28.26,39.4 28.1,39.4 27.99,39.29 27.99,39.13 28.98,38.13 28.98,37.97 28.71,37.7 28.71,37.17 28.6,37.05 28.14,37.05 28.03,36.94 28.03,36.78 28.14,36.67 28.6,36.67 28.71,36.56 28.71,36.4 28.6,36.29 28.14,36.29 28.03,36.18 28.03,36.02 28.14,35.91 28.6,35.91 28.71,35.8 28.71,35.64 28.6,35.53 28.14,35.53 28.03,35.42 28.03,35.26 28.14,35.15 28.6,35.15 28.71,35.04 28.71,34.66 28.31,34.25 23.75,34.25 23.46,34.54 R595.1
PTD12/MII_RMII_TX_EN: length 104.3
  TOP w0.406: R91.2 103.16,66.51 102.81,66.15 v1(101.69,66.15) ; R208.2 v1(34.26,44.28)
  L6_INT_2 w0.191: v1(101.69,66.15) 101.35,65.81 101.35,65.33 101.26,65.24 99.71,65.24 99.62,65.14 99.62,65.01 99.71,64.92 101.26,64.92 101.35,64.83 101.35,64.7 101.26,64.6 99.71,64.6 99.62,64.51 99.62,64.38 99.71,64.28 101.26,64.28 101.35,64.19 101.35,64.06 101.26,63.97 99.71,63.97 99.62,63.87 99.62,63.74 99.71,63.65 101.26,63.65 101.35,63.56 101.35,61.45 97.9,58 96.95,57.04 96.95,57.03 96.29,56.38 96.28,56.38 96.22,56.32 93.81,56.32 88.57,51.08 88.57,44.16 85.09,40.68 56.71,40.68 56.13,40.1 50.73,40.1 49.79,41.04 47.38,41.04 47.14,40.79 43.09,40.79 41.66,39.36 39.51,39.36 38.1,37.95 37.4,37.95 36.21,39.15 36.21,42.34 v1(34.26,44.28)
PTD12/MII_RMII_TX_EN/QSPI_A_I_1: length 4.4
  TOP w0.279: U11.13 37.57,51.33 v1(37.43,51.47) 37.07,51.83 36.74,51.83 R165.2
  BOTTOM w0.279: v1(37.43,51.47) 37.07,51.83 36.74,51.83 R165.2
PTD12/MII_RMII_TX_EN/QSPI_A_I_2: length 30.6
  TOP w0.16: U8.55 v1(54.18,59.43) ; U7.47 v1(59.45,57.43)
  TOP w0.406: R165.1 36.16,54.09 v1(36.56,54.49)
  L3_INT_1 w0.191: v1(36.56,54.49) 36.72,54.65 37.55,54.65 37.98,54.22 41.77,54.22 46.68,59.13 51.68,59.13 51.85,59.29 52.74,59.29
  L3_INT_1 w0.203: v1(54.18,59.43) 53.43,59.43 53.29,59.29 52.74,59.29
  BOTTOM w0.16: v1(59.45,57.43) 57.14,57.43 55.14,59.43 v1(54.18,59.43)
PTD12/MII_RMII_TX_EN/QSPI_A_IO2: length 5.2
  TOP w0.279: R208.1 R209.1 v1(36.84,46.11) 37.36,46.11 37.57,46.32 U11.2
  BOTTOM w0.406: v1(36.84,46.11) 37.3,46.57 37.5,46.57 R566.2
PTD12/QSPI_A_IO2: length 48.1
  TOP w0.279: v1(34.28,43.52) 35.27,43.52 R209.2
  BOTTOM w0.254: R590.1 36.79,35.63 36,34.85 36,34.69 36.21,34.48 36.21,34.33 36.1,34.21 35.94,34.21 35.73,34.42 35.58,34.42 35.19,34.04 35.19,32.76 35.08,32.65 34.93,32.65 34.81,32.76 34.81,34.04 34.7,34.15 34.54,34.15 34.43,34.04 34.43,32.76 34.32,32.65 34.16,32.65 34.05,32.76 34.05,34.04 33.94,34.15 33.56,34.15 33.45,34.04 33.45,33.19 33.34,33.08 33.18,33.08 33.07,33.19 33.07,34.04 32.95,34.15 32.8,34.15 32.69,34.04 32.69,33.19 32.57,33.08 32.42,33.08 32.3,33.19 32.3,34.04 32.19,34.15 31.81,34.15 31.7,34.04 31.7,33.58 31.59,33.47 31.43,33.47 31.32,33.58 31.32,33.89 31.07,34.15 29.6,34.15 29.35,34.4 29.35,35.11 29.46,35.22 30.99,35.22 31.1,35.34 31.1,35.49 30.99,35.61 29.46,35.61 29.35,35.72 29.35,35.87 29.46,35.99 30.99,35.99 31.1,36.1 31.1,36.26 30.99,36.37 29.46,36.37 29.35,36.48 29.35,37.7 30.84,39.2 31,39.2 31.7,38.51 31.85,38.51 31.97,38.62 31.97,38.78 31.27,39.47 31.27,39.63 32.37,40.72 32.52,40.72 33.52,39.72 33.68,39.72 33.79,39.83 33.79,39.99 32.79,40.99 32.79,41.15 33.06,41.42 33.22,41.42 34.36,40.28 34.52,40.28 34.63,40.39 34.63,40.55 33.49,41.69 33.49,41.84 34.28,42.63 v1(34.28,43.52)
PTD13/FTM2_CH4/LPUART1_RX/ENET_: length 139.2
  TOP w0.16: v1(61.05,61.63) 60.29,62.39 U7.35 ; U8.42 v1(58.78,67.57)
  TOP w0.406: v1(86.09,35.14) 87.01,34.22 89.57,34.22 90.79,33.01 96.79,33.01 98.26,31.53 98.26,27.24 97.65,26.63 J5.20 ; R317.1 v1(50.51,12.14)
  L3_INT_1 w0.191: 83.93,53.47 85.43,51.97 85.43,47.91 85.83,47.5 85.83,47.11 85.41,46.69 85.41,44.58 86.09,43.9 v1(86.09,35.14) ; v1(50.51,12.14) 51.43,11.22 82.12,11.22 96.48,25.58 J5.20
  L3_INT_1 w0.203: 83.93,53.47 82.93,54.47 82.93,54.91 82.65,55.19 82.49,55.19 80.91,56.77 80.91,61.75 78.06,64.6 61.27,64.6 58.78,67.09 v1(58.78,67.57)
  BOTTOM w0.16: v1(61.05,61.63) 61.05,62.09 60.29,62.85 60.29,64.09 58.78,65.6 v1(58.78,67.57)
PTD14/FTM2_CH5/LPUART1_TX/ENET_: length 124.4
  TOP w0.16: U8.41 v1(59.28,68.04) ; U7.34 v1(60.79,63.24)
  TOP w0.406: R322.1 v1(63.21,12.33)
  L3_INT_1 w0.191: 83.93,54.06 86.72,51.27 86.72,48.49 86.43,48.2 86.43,41.98 86.57,41.84 86.57,34.42 v1(82.89,30.74)
  L3_INT_1 w0.203: v1(59.28,68.04) 59.28,67.39 61.72,64.96 78.21,64.96 81.34,61.82 81.34,56.84 82.64,55.55 82.79,55.55 83.29,55.06 83.29,54.71 83.93,54.06
  L6_INT_2 w0.191: J1.22 45.68,74.48 51.87,68.29 54.07,68.29 54.41,67.95 56.1,67.95 56.43,67.63 56.95,67.63
  L6_INT_2 w0.203: 56.95,67.63 58.08,67.63 58.51,68.06 59.27,68.06 v1(59.28,68.04)
  BOTTOM w0.16: v1(60.79,63.24) 60.79,64.35 59.28,65.86 v1(59.28,68.04)
  BOTTOM w0.406: v1(63.21,12.33) 64.27,11.26 75.96,11.26 82.48,17.78 82.48,30.33 v1(82.89,30.74)
PTD15/FTM0_CH0/TRACE_D3/LPSPI0_: length 202.7
  TOP w0.16: U8.36 v1(61.79,67.57) ; U7.29 v1(63.29,62.77)
  TOP w0.406: R148.2 v1(95.08,55.43) ; R332.1 v1(29.41,10.25)
  L3_INT_1 w0.191: v1(29.41,10.25) 81.65,10.25 96.92,25.52 96.94,25.52 97.59,26.17 97.59,26.19 97.75,26.35 97.75,38.4 100.9,41.55 100.9,41.94 100.62,42.22 98.67,42.22 95.26,45.64 93.77,45.64 93.2,46.21 93.2,52.91 93.36,53.08 93.38,53.08 93.66,53.36 93.66,53.37 95.08,54.8 v1(95.08,55.43) 96.4,56.75 96.4,60.34 96.31,60.43 96.31,61.27 97.19,62.15 97.35,62.15 98.13,62.92 98.13,71.28 96.22,73.19 92.93,73.19 85.99,66.25 83.93,66.25
  L3_INT_1 w0.203: v1(61.79,67.57) 61.79,67.09 63.56,65.31 81.7,65.31 82.64,66.25 83.93,66.25
  L6_INT_2 w0.191: 58.06,69.05 58.16,69.15 60.86,69.15 60.97,69.05 ; J1.19 46.96,76.17 46.96,73.65 51.97,68.63 52.74,68.63
  L6_INT_2 w0.203: 52.74,68.63 54.22,68.63 54.49,68.36 57.37,68.36 58.06,69.05 ; v1(61.79,67.57) 61.79,68.23 60.97,69.05
  BOTTOM w0.16: v1(63.29,62.77) 63.29,64.8 61.79,66.31 v1(61.79,67.57)
PTD16/FTM0_CH1/TRACE_D2/LPSPI0_: length 94.2
  TOP w0.16: U8.35 v1(62.29,68.04) ; U7.28 v1(63.79,63.24)
  TOP w0.406: R114.2 96.56,61.3 v1(96.79,61.07)
  L3_INT_1 w0.191: v1(96.79,61.07) 98.44,62.73 98.44,71.41 95.57,74.28 93.57,74.28 86,66.71 83.93,66.71
  L3_INT_1 w0.203: 83.93,66.71 82.44,66.71 81.39,65.67 64.01,65.67 62.29,67.39 v1(62.29,68.04)
  L6_INT_2 w0.191: 52.74,67.94 51.77,67.94 44.58,75.13 44.58,77.88 45.23,78.53 49.66,78.53 J1.16
  L6_INT_2 w0.203: v1(62.29,68.04) 62.29,67.39 61.99,67.09 56.47,67.09 55.96,67.6 54.26,67.6 53.93,67.94 52.74,67.94
  BOTTOM w0.16: v1(63.79,63.24) 63.79,64.78 62.29,66.29 v1(62.29,68.04)
PTD17/FTM0_FLT2/LPUART2_RX/FTM5: length 25
  TOP w0.16: U8.32 v1(63.79,67.57) ; U7.25 v1(65.29,62.77)
  L3_INT_1 w0.191: v1(63.79,67.57) 63.79,69.3 63.89,69.4 v1(63.89,71.08)
  L6_INT_2 w0.191: v1(63.89,71.08) 60.61,71.08 57.48,74.21 56.52,74.21 J1.13
  BOTTOM w0.16: v1(65.29,62.77) 65.29,64.77 63.79,66.27 v1(63.79,67.57)
PTD18/FTM5_CH7/FXIO_D2/LPI2C1_S: length 97.2
  TOP w0.16: 66.79,40.98 v1(66.79,39.79) ; v1(67.03,45.22) 67.03,44.76 67.04,44.75 67.04,44.57 67.29,44.32 U7.88
  TOP w0.406: v1(60.68,17.78) 61.41,17.78 67.32,23.69 67.32,29.67 67.4,29.75 v1(67.4,30.44) ; R321.1 v1(60.67,12.37)
  L3_INT_1 w0.191: v1(80.2,75.88) 77.71,75.88 J6.19 ; v1(67.4,30.44) 67.4,38.01 66.79,38.62 ; v1(60.67,12.37) 60.67,12.85 60.68,12.86 v1(60.68,17.78)
  L3_INT_1 w0.203: 66.79,38.62 v1(66.79,39.79)
  BOTTOM w0.16: v1(67.03,45.22) 67.03,44.58 67.25,44.35 67.25,40.25 v1(66.79,39.79)
  BOTTOM w0.203: v1(80.2,75.88) 80.2,75.4 81.52,74.08 86.84,74.08 87.87,73.04 87.87,67.41 87.85,67.39 87.85,57.46 82.9,52.51 81.85,52.51 79.75,50.41 77.9,50.41 77.03,49.54 70.05,49.54 67.03,46.52 v1(67.03,45.22)
PTD19/FTM6_CH0/FXIO_D3/LPI2C1_S: length 144.1
  TOP w0.16: v1(67.56,44.78) 67.88,44.46 67.88,44.28 67.79,44.19 U7.89 ; 67.29,40.98 v1(67.29,39.32)
  TOP w0.406: R314.1 v1(42.89,12.14)
  L3_INT_1 w0.191: J6.22 72.51,78.54 72.51,82.65 71.54,83.62 66.4,83.62 v1(66,83.22)
  L3_INT_1 w0.203: v1(67.29,39.32) 67.29,39.97 66.99,40.27 53.99,40.27 v1(52.92,39.2)
  L6_INT_2 w0.191: 52.74,63.01 48.5,58.77 46.85,58.77 46.3,58.22 46.3,49.09 53.23,42.16 55.28,42.16 55.95,42.83 57.96,42.83
  L6_INT_2 w0.203: 52.74,63.01 52.78,63.05 v1(53.27,63.05) ; v1(67.56,44.78) 67.56,44.29 67.55,44.29 67.55,43.88 66.5,42.83 57.96,42.83
  BOTTOM w0.16: v1(67.29,39.32) 67.29,39.78 67.75,40.24 67.75,44.59 v1(67.56,44.78)
  BOTTOM w0.203: v1(53.27,63.05) 53.27,63.54 53.12,63.68 53.12,67.47 54.37,68.72 54.37,69.05 ; 52.92,38.62 v1(52.92,39.2)
  BOTTOM w0.406: v1(66,83.22) 64.05,81.27 57.97,81.27 57.06,80.36 57.06,76.62 56.38,75.93 56.38,75.53 54.37,73.53 54.37,69.05 ; v1(42.89,12.14) 44.12,12.14 47.76,15.78 47.76,23.06 50.04,25.33 51.19,25.33 52.08,26.23 52.08,34.4 52.92,35.24 52.92,38.62
PTD20/FTM6_CH1: length 64.9
  TOP w0.203: v1(69.89,38.77) 69.89,39.43 69.79,39.53 69.79,40.98
  L3_INT_1 w0.191: v1(53.4,45.68) 53.38,45.68 53.4,45.65 53.4,45.49 54.45,44.45 54.8,44.45 55.32,43.92 55.32,43.41 58.01,40.72 68.56,40.72 69.89,39.4 v1(69.89,38.77)
  BOTTOM w0.203: v1(53.4,45.68) 53.06,46.02 53.04,46.02 50.26,48.8 50.26,49.51 49.19,50.58 49.19,52.46 44.08,57.57 44.08,59.95 42.71,61.33 42.71,73.37 43.81,74.47 43.81,80.64 J1.24
PTD21/FTM6_CH2: length 65.3
  TOP w0.203: 71.79,40.98 v1(71.79,39.23)
  L3_INT_1 w0.191: v1(71.79,39.23) 71.79,39.96 70.65,41.11 58.11,41.11 55.66,43.55 55.66,64.07 54.77,64.96 52.39,64.96 50.38,66.96 v1(49.2,66.96)
  BOTTOM w0.191: J1.21 47.11,81.4 47.11,76.4 49.36,74.14 49.36,67.6 49.2,67.44 v1(49.2,66.96)
PTD22/FTM6_CH3/FTM6_CH3/ADC1_SE: length 36.9
  TOP w0.16: 73.3,40.98 v1(73.3,39.79) ; U7.99 v1(72.79,44.12)
  L3_INT_1 w0.191: 73.3,38.62 72.8,38.13 72.8,38.09 72.52,37.81 72.49,37.81 70.5,35.82 70.5,29.57 68.68,27.75 56.74,27.75 56.45,28.05 54.72,28.05 J4.5
  L3_INT_1 w0.203: v1(73.3,39.79) 73.3,38.62
  BOTTOM w0.16: v1(73.3,39.79) 73.3,40.67 72.79,41.18 v1(72.79,44.12)
PTD23/FTM6_CH4/FTM6_CH4/ADC1_SE: length 38.1
  TOP w0.16: 75.3,40.98 v1(75.3,39.79) ; U7.103 v1(74.79,44.12)
  L3_INT_1 w0.191: 74.38,38.62 71.22,35.46 71.22,27.31 69.13,25.21 57.26,25.21 J4.8
  L3_INT_1 w0.203: 74.38,38.62 74.78,38.62 75.3,39.14 v1(75.3,39.79)
  BOTTOM w0.16: v1(75.3,39.79) 75.3,41.97 74.79,42.48 v1(74.79,44.12)
PTD24/FTM6_CH5/FTM6_CH5/ADC1_SE: length 40.1
  TOP w0.16: U7.106 76.29,44.33 76.11,44.51 v1(76.11,44.97) ; 76.8,40.98 v1(76.8,39.32)
  L3_INT_1 w0.191: v1(71.18,25.46) 71.54,25.82 71.54,35.33 73.96,37.75 75.23,37.75 76.1,38.62
  L3_INT_1 w0.203: v1(76.8,39.32) 76.1,38.62
  L6_INT_2 w0.191: v1(71.18,25.46) 69.39,25.46 69.13,25.2 59.81,25.2 J4.11
  BOTTOM w0.16: v1(76.11,44.97) 76.11,44.51 76.29,44.33 76.29,43.01 76.8,42.5 v1(76.8,39.32)
PTD25/FTM6_CH6: length 96.5
  TOP w0.203: v1(79.38,39.68) 79.3,39.76 79.3,40.98
  L3_INT_1 w0.191: 52.74,65.31 52.6,65.31 45.04,72.86 27.06,72.86 23.66,76.26 20.94,76.26 20.86,76.19 v1(20.38,76.19)
  L3_INT_1 w0.203: 52.74,65.31 54.92,65.31 56.01,64.21 56.01,43.7 58.2,41.51 77.56,41.51 v1(79.38,39.68)
  L6_INT_2 w0.191: v1(20.38,76.19) 20.05,76.52 20.05,80.29 20.87,81.11 22.44,81.11 J2.24
PTD26/FTM6_CH7/FXIO_D7: length 93.7
  TOP w0.203: U8.134 82.64,43.42 82.69,43.47 82.87,43.47 82.97,43.57 v1(83.45,43.57)
  L3_INT_1 w0.191: 55.7,69.05 55.01,69.74 55.01,70.78 52.5,73.29 50.42,73.29 48.42,75.29 47.66,75.29 47.63,75.32 46.24,75.32 44.16,77.4 44.16,80.25 v1(43.01,81.39)
  L3_INT_1 w0.203: 55.7,69.05 56.21,68.54 56.24,68.54 60.89,63.89 76.82,63.89 77.27,63.44 77.27,63.04 77.15,62.91 77.15,61.94 77.46,61.63 77.46,61.23 77.15,60.92 77.15,58.82 80.25,55.72 80.25,54.48 82.37,52.36 82.92,52.36 83.88,51.39 83.88,44 v1(83.45,43.57)
  L6_INT_2 w0.191: v1(43.01,81.39) 43.01,82.84 42.25,83.61 22.4,83.61 J2.27
PTD27/FTM7_CH0/FTM7_CH0/ADC1_SE: length 43.6
  TOP w0.16: U8.135 v1(82.44,43.92) ; v1(76.92,46.29) 77.25,45.96 77.25,45.91 77.57,45.59 77.78,45.59 77.94,45.43 U7.110
  BOTTOM w0.16: v1(76.92,46.29) 76.92,46.24 77.05,46.12 77.05,46.07 77.68,45.43 78.7,45.43 80.2,43.92 v1(82.44,43.92)
  BOTTOM w0.191: v1(82.44,43.92) 83.13,43.92 83.25,44.05 83.74,44.05 83.95,43.84 83.95,43.38 80.2,39.63 80.2,39.34 77.6,36.75 75.29,36.75 70.4,31.86 68.34,31.86 67.78,31.3 64.04,31.3 62.29,29.55 62.29,28 J4.14
PTD28/FTM7_CH1/FTM7_CH1/ADC1_SE: length 40
  TOP w0.16: U8.137 v1(82.44,44.92) ; U7.112 v1(77.63,46.43)
  BOTTOM w0.16: v1(77.63,46.43) 79.47,46.43 80.98,44.92 v1(82.44,44.92)
  BOTTOM w0.191: J4.17 64.9,28.07 64.9,29.62 66.25,30.97 68.26,30.97 68.82,31.53 70.55,31.53 75.45,36.43 77.77,36.43 80.54,39.2 80.54,39.48 84.28,43.22 84.28,44.07 83.42,44.92 v1(82.44,44.92)
PTD29/FTM7_CH2/FTM7_CH2/ADC1_SE: length 60.8
  TOP w0.16: U7.114 v1(77.63,47.43) ; U8.139 82.44,45.92 v1(82.44,45.9)
  L3_INT_1 w0.191: v1(93.43,54.82) 89.8,54.82 v1(89.45,55.18)
  L6_INT_2 w0.191: 83.93,46.45 84.14,46.65 84.14,47.74 85.5,49.1 85.5,49.64 85.85,49.98 86.11,49.98 86.39,50.26 86.39,51.6 86.66,51.87 89.45,54.65 v1(89.45,55.18)
  L6_INT_2 w0.203: v1(82.44,45.9) 83.39,45.9 83.93,46.45
  BOTTOM w0.16: v1(77.63,47.43) 79.62,47.43 81.15,45.9 v1(82.44,45.9)
  BOTTOM w0.191: J4.20 67.44,28.07 67.44,29.62 68.13,30.31 69.78,30.31 75.52,36.05 77.88,36.05 80.88,39.06 80.88,39.28 84.59,42.99 84.59,44.41 83.1,45.9 v1(82.44,45.9)
  BOTTOM w0.406: v1(93.43,54.82) 93.85,54.41 93.85,53.04 94.63,52.26 R549.1
PTD30/FTM7_CH3/FTM6_FLT1/ADC1_S: length 46.9
  TOP w0.16: v1(82.44,46.92) 82.43,46.93 U8.141 ; U7.116 v1(77.63,48.43)
  BOTTOM w0.16: v1(82.44,46.92) 81.27,46.92 79.76,48.43 v1(77.63,48.43)
  BOTTOM w0.191: J4.23 71.51,29.6 71.51,30.7 74.68,33.87 78.54,33.87 79.32,34.66 84.04,34.66 87.92,38.54 87.92,45.42 85.55,47.78 84.44,47.78 84.16,47.51 83.02,47.51 v1(82.44,46.92)
PTD31/FTM7_CH4/FXIO_D6/FTM6_FLT: length 101
  TOP w0.203: U8.142 82.23,47.43 82.24,47.41 84.36,47.41 84.44,47.33 84.85,47.33 84.87,47.31 v1(85.36,47.31)
  L3_INT_1 w0.191: v1(40.28,61.08) 39.81,61.08 39.74,61.15 34.36,61.15 31.71,63.8 31.21,63.8 27.77,67.23 27.77,69.09 22.07,74.79 20.38,74.79 18.96,76.21 18.42,76.21 17.66,76.97 17.66,81.41 J2.30
  L6_INT_2 w0.191: v1(85.36,47.31) 85.36,44.79 82.97,42.4 56,42.4 55.42,41.81 53.09,41.81 45.83,49.07 45.83,55.53 v1(40.28,61.08)
PTE0/LPSPI0_SCK/TCLK1/LPI2C1_SD: length 62.1
  TOP w0.16: U8.166 v1(82.44,59.43)
  TOP w0.203: U7.138 80.25,59.43 80.25,59.43 U8.166
  TOP w0.406: R328.1 v1(78.45,12.33) 78.45,13.68 J5.16
  L3_INT_1 w0.191: J5.16 92.65,27.87 92.65,41.42 91.35,42.72 91.35,51.7 84.8,58.25 84.25,58.25 83.93,58.57
  L3_INT_1 w0.203: 83.93,58.57 83.34,59.16 83.34,59.19 83.09,59.43 v1(82.44,59.43)
PTE1/LPSPI0_SIN/LPI2C0_HREQ/LPI: length 60.4
  TOP w0.16: U8.165 v1(82.91,58.93)
  TOP w0.203: U7.137 80.25,58.93 80.25,58.93 U8.165
  TOP w0.406: J5.14 75.91,13.68 v1(75.91,12.33) R327.1
  L3_INT_1 w0.191: J5.14 89.96,27.73 89.96,28.7 89.97,28.71 89.97,29.63 89.96,29.64 89.96,48.47 88.96,49.46 88.96,53.64 84.7,57.91 83.93,57.91
  L3_INT_1 w0.203: 83.93,57.91 v1(82.91,58.93)
PTE2/LPSPI0_SOUT/FTM3_CH6/SAI1_: length 128.8
  TOP w0.203: U7.122 80.25,51.43 80.25,51.43 U8.150 82.27,51.43 v1(82.72,51.88)
  TOP w0.406: v1(79.59,30.69) 75.53,30.69 74.84,30.01 74.84,28.17 74.83,28.16 74.83,27.15 74.84,27.13 74.84,26.12 74.13,25.41 74.11,25.41 62.88,14.18 54.95,14.18 54.09,13.32 49.15,13.32 v1(47.97,12.14) R316.1
  L3_INT_1 w0.191: 83.69,38.62 83.69,37.92 82.23,36.45 82.23,34.25 80.88,32.9 80.88,31.98 v1(79.59,30.69)
  L3_INT_1 w0.203: v1(82.72,51.88) 81.61,50.77 81.61,42.91 83.69,40.82 83.69,38.62
  L6_INT_2 w0.191: J1.17 51.86,81.07 53.76,81.07 54.74,80.09 54.74,76.98 56.87,74.85 57.73,74.85 57.73,74.85 57.74,74.85 60.71,71.87 64.31,71.87 66.41,69.77 72.53,69.77 73.09,69.22 81.69,69.22 85.35,65.56 85.35,65.53 85.95,64.93 85.95,64.92 85.95,55.12
  L6_INT_2 w0.203: 85.95,55.12 v1(82.72,51.88)
PTE3/FTM0_FLT0/FTM2_FLT0/CMP0_O: length 28.4
  TOP w0.16: U7.21 v1(67.29,62.77) ; U8.28 v1(65.79,67.57)
  L3_INT_1 w0.191: v1(65.79,67.57) 65.79,69.69 v1(65.37,70.11)
  L6_INT_2 w0.191: J1.14 54.42,78.85 54.42,76.85 56.73,74.53 57.59,74.53 57.6,74.53 57.61,74.53 60.58,71.56 64.09,71.56 65.03,70.62 65.03,70.45 v1(65.37,70.11)
  BOTTOM w0.16: v1(65.79,67.57) 65.79,66.27 67.29,64.77 v1(67.29,62.77)
PTE4/CAN0_RX_LS: length 12.6
  TOP w0.203: R127.1 20.66,61.17 TP13.1 19.57,61.71 19.32,61.45 19.32,61.15 v1(19.31,61.15)
  L3_INT_1 w0.203: v1(16.17,56.2) 16.17,59.03 17.4,60.27 19.12,60.27 19.31,60.46 v1(19.31,61.15)
  BOTTOM w0.203: U502.6 16.44,57.7 16.76,57.38 16.76,56.54 16.42,56.2 v1(16.17,56.2)
PTE4/TRACE_D1/FTM2_CH2/CAN0_RX/: length 114.9
  TOP w0.16: U8.15 v1(72.29,68.04) ; U7.9 v1(73.29,62.77)
  TOP w0.406: R136.2 v1(95.87,58.76)
  L6_INT_2 w0.191: v1(16.68,62.7) 17.15,62.7 17.56,63.1 21.13,63.1 24.39,66.36 24.39,68.24 24.89,68.74 26.21,68.74 30.29,64.65 42.14,64.65 42.65,64.14 44.91,64.14 46.11,65.34 v1(46.11,66.51) ; 61.65,69.78 61.33,70.11 58.59,70.11 57.35,71.35 54,71.35 53.56,70.91 52.15,70.91 49.73,73.33 v1(48.55,73.33) ; v1(75.76,73.14) 81.5,73.14 v1(95.87,58.76)
  L6_INT_2 w0.203: v1(72.29,68.04) 71.57,68.77 64.15,68.77 63.13,69.78 61.65,69.78
  BOTTOM w0.16: v1(72.29,68.04) 72.29,65.55 73.29,64.55 v1(73.29,62.77)
  BOTTOM w0.191: v1(48.55,73.33) 49.05,72.83 49.05,68.47 48.99,68.42 48.99,68.42 48.67,68.1 48.67,68.1 47.08,66.51 v1(46.11,66.51)
  BOTTOM w0.203: 72.29,69.05 v1(72.29,68.04) ; v1(16.68,62.7) 16.5,62.52 R520.1
  BOTTOM w0.406: v1(75.76,73.14) 72.29,69.68 72.29,69.05
PTE5/CAN0_TX_LS: length 9.5
  TOP w0.203: v1(18.69,60.78) 19.03,60.44 19.09,60.44 19.11,60.41 R126.1
  L3_INT_1 w0.203: v1(15.46,56.47) 15.46,58.79 17.45,60.78 v1(18.69,60.78)
  BOTTOM w0.203: v1(15.46,56.47) TP504.1 U502.7
PTE5/TCLK2/FTM2_CH3/CAN0_TX/FXI: length 81.9
  TOP w0.16: U8.14 v1(72.8,67.57) ; U7.8 v1(73.79,63.24)
  TOP w0.406: v1(37.3,72.04) 37.3,75.15 38.2,76.05 40.43,76.05 41.64,74.84 v1(47.43,74.84)
  L6_INT_2 w0.191: 71.97,69.05 71.9,69.12 64.29,69.12 63.3,70.11 61.78,70.11 61.46,70.43 58.78,70.43 57.54,71.67 53.87,71.67 53.43,71.23 52.77,71.23 50.19,73.8 48.35,73.8 47.82,74.34 47.82,74.45 v1(47.43,74.84) ; v1(13.4,61.86) 14.67,61.86 16.73,63.92 21.05,63.92 23.03,65.9 23.03,68.02 25.35,70.34 36.07,70.34 37.3,71.57 v1(37.3,72.04)
  L6_INT_2 w0.203: 71.97,69.05 72.8,68.23 v1(72.8,67.57)
  BOTTOM w0.16: v1(73.79,63.24) 73.79,64.81 72.8,65.81 v1(72.8,67.57)
  BOTTOM w0.203: R519.1 13.65,62.11 v1(13.4,61.86)
PTE6/LPSPI0_PCS2/FTM7_FLT1/FTM3: length 57.6
  TOP w0.203: U7.121 80.25,50.93 80.25,50.93 U8.149 82.33,50.93 82.72,51.32 v1(83.25,51.32)
  L6_INT_2 w0.191: 83.93,67.73 86.28,65.38 86.28,54.86 83.93,52.51 ; J1.11 56.94,78.87 56.94,76.09 57.86,75.16 57.87,75.16 60.84,72.19 64.44,72.19 66.54,70.09 72.66,70.09 73.15,69.61 82.05,69.61 82.61,69.05
  L6_INT_2 w0.203: v1(83.25,51.32) 83.25,51.83 83.93,52.51 ; 82.61,69.05 83.93,67.73
PTE7/FTM0_CH7/FTM3_FLT0: length 62.9
  TOP w0.16: U7.87 v1(66.79,44.12) ; 66.29,40.98 v1(66.29,39.32)
  L3_INT_1 w0.191: 55.2,69.05 53.1,71.15 v1(53.1,72.02)
  L3_INT_1 w0.203: 55.2,69.05 56.06,68.18 56.07,68.18 60.27,63.98 60.27,55.8 60.4,55.67 60.4,55.19 60.21,55 60.21,49.35 64.44,45.12 66.45,45.12 66.79,44.78 v1(66.79,44.12)
  L6_INT_2 w0.191: v1(53.1,72.02) 52.19,72.93 52.19,78 51.34,78.86 50.32,78.86 49.66,79.51 49.66,80.42 50.62,81.39 56.97,81.39 J1.8
  BOTTOM w0.16: v1(66.79,44.12) 66.79,40.44 66.29,39.94 v1(66.29,39.32)
PTE8/FTM0_CH6/MII_RMII_MDC/CMP0: length 32.2
  TOP w0.16: v1(53.95,63.08) 53.96,63.08 53.96,63.28 54.12,63.44 U8.47 ; v1(59.74,61.14) 59.94,61.14 59.65,61.43 U7.39
  BOTTOM w0.16: v1(53.95,63.08) 54.28,63.41 55.64,63.41 57.58,61.46 59.42,61.46 v1(59.74,61.14)
  BOTTOM w0.203: 54.9,69.05 54.9,68.54 53.48,67.12 53.48,64.04 53.95,63.57 v1(53.95,63.08)
  BOTTOM w0.406: J1.5 59.72,78.76 59.72,77.06 56.89,74.23 55.83,74.23 54.9,73.3 54.9,69.05
PTE9/FTM0_CH7/LPUART2_CTS/ENET_: length 152.9
  TOP w0.16: U7.30 v1(62.79,63.24) ; U8.37 v1(61.29,68.04)
  TOP w0.406: R331.1 v1(26.12,11)
  L3_INT_1 w0.191: v1(26.12,11) 26.6,11 26.76,10.84 27.71,10.84 27.91,11.05 36.46,11.05 39.17,13.76 39.17,19.94 37.03,22.08 31.23,22.08 30.32,22.99 29.99,22.99 29.34,23.63 29.34,27.08 30,27.74 30.57,27.74 31.74,28.91 31.74,29.73 32.47,30.47 v1(32.47,31.51) ; J1.2 64.57,78.86 64.57,73.16 62.29,70.87 62.29,69.05
  L3_INT_1 w0.203: 62.29,69.05 v1(61.29,68.04)
  L6_INT_2 w0.191: 52.74,63.89 52.56,64.08 50.59,64.08 50.02,63.5 42.39,63.5 41.87,64.02 25.47,64.02 23.28,61.83 23.28,60.69 22.26,59.68 16.77,59.68 15.47,58.37 13.4,58.37 12.85,57.82 12.85,55.02 16.95,50.92 17.33,50.92 19.67,48.57 19.67,44.29 32,31.96 32.02,31.96 v1(32.47,31.51)
  L6_INT_2 w0.203: 52.74,63.89 53.98,63.89 54.37,63.51 54.77,63.51 54.98,63.72 62.31,63.72 v1(62.79,63.24)
  BOTTOM w0.16: v1(62.79,63.24) 62.79,64.83 61.29,66.33 v1(61.29,68.04)
